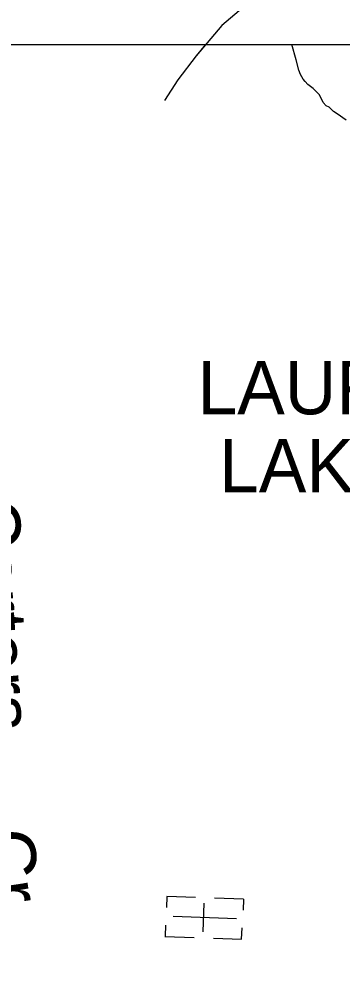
# Model space of a CAD drawing. Extents: x 1577619 to 1828281, y 483481 to 598136.
# Drawn here: x 1672781 to 1675660, y 518314 to 526740 of the extents above; entities that cross this region are included whole.
import ezdxf

# ---------------------------------------------------------------- set-up
doc = ezdxf.new("R2010")
doc.units = 0
for name, color, linetype in [('DESIGN - CONTOURS - Intermediate with optional Text', 7, 'Continuous'), ('DESIGN - DRAINAGE - Bridges and Cross Drains Size Text', 7, 'Continuous'), ('DESIGN - SHEET - Linework', 7, 'Continuous'), ('DESIGN - TRANSPORTATION - Text', 7, 'Continuous'), ('DESIGN - UTILITIES - Cable (Underground) with Text', 7, 'Continuous')]:
    doc.layers.add(name, color=color, linetype=linetype)

msp = doc.modelspace()

# ---------------------------------------------------------------- linework, layer by layer
at = {"layer": 'DESIGN - CONTOURS - Intermediate with optional Text'}
for points in [[(1675325.7, 527307), (1674587.8, 526682.3), (1674360.7, 526411), (1674196.7, 526196.4), (1674076.9, 526013.4)], [(1675325.7, 527307), (1674587.8, 526682.3), (1674360.7, 526411), (1674196.7, 526196.4), (1674076.9, 526013.4)], [(1674444.2, 526510.7), (1674360.7, 526411), (1674196.7, 526196.4), (1674076.9, 526013.4)], [(1674444.2, 526510.7), (1674360.7, 526411), (1674196.7, 526196.4), (1674076.9, 526013.4)]]:
    msp.add_lwpolyline(points, dxfattribs=at)
at = {"layer": 'DESIGN - SHEET - Linework'}
msp.add_lwpolyline([(1669171.5, 526510.7), (1695618, 526510.7), (1695618, 508119.9), (1669171.5, 508119.9)], close=True, dxfattribs=at)
at = {"layer": 'DESIGN - TRANSPORTATION - Text'}
msp.add_lwpolyline([(1675696.6, 525836.2), (1675615.2, 525893.2), (1675583.4, 525915.6), (1675543.7, 525952.1), (1675517.9, 525966.4), (1675490.2, 525994.8), (1675482.4, 526016.9), (1675456.9, 526065.3), (1675401.4, 526120), (1675353.8, 526154.6), (1675330, 526181), (1675314.3, 526203.2), (1675288.7, 526243.6), (1675273.1, 526283.8), (1675250.1, 526376.3), (1675212.6, 526510.7)], dxfattribs=at)
at = {"layer": 'DESIGN - UTILITIES - Cable (Underground) with Text'}
for p, q in [((1674098.7, 518917.2), (1674095.2, 518817.5)), ((1674355.1, 518908.2), (1674098.7, 518917.1)), ((1674781.5, 518893.3), (1674523.5, 518902.3)), ((1674781.5, 518893.2), (1674777.9, 518793.5)), ((1674427.9, 518855.6), (1674419.1, 518602.1)), ((1674085.6, 518660.8), (1674082.3, 518561.7)), ((1674765, 518537.5), (1674768.3, 518635.8)), ((1674082.2, 518561.1), (1674343, 518552.1)), ((1674513.5, 518546.1), (1674765, 518537.3))]:
    msp.add_line(p, q, dxfattribs=at)
msp.add_lwpolyline([(1674155.9, 518739.8), (1674718.4, 518720)], dxfattribs=at)

# ---------------------------------------------------------------- texts
at = {"layer": 'DESIGN - DRAINAGE - Bridges and Cross Drains Size Text'}
for s, height, rotation, p in [('LAURA', 475.19, 0.00003, (1674372.2, 523215)), ('LAKE', 475.19, 0.00003, (1674564.4, 522519.4)), ('Carters', 475.01, 273.87051, (1672303.4, 522455.4)), ('Cr.', 475.01, 278.1803, (1672425.5, 519484.1))]:
    msp.add_text(s, height=height, rotation=rotation, dxfattribs=at).set_placement(p)

doc.saveas('drawing.dxf')
